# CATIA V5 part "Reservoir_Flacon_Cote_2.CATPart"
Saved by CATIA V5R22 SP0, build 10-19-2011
Part number: Reservoir_Flacon_Cote
Bounding box of the stored display mesh (mm): x 0 to 5, y -31 to 31, z -150 to 150
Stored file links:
  D:\CAO_PER_MODIF_2025\CAO_PER_pick&place_2024P\Sous_Ensemble_Flacon\Reservoir_Flacon\Reservoir_Flacon_Cote_2.CATPart
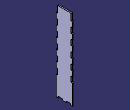
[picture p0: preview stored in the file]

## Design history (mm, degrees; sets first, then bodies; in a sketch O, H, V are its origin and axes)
Body1 (main body)
  Sketch1 on yz-plane, origin (0, 0, 0), H (0, 1, 0), V (0, 0, 1)
    line L1 (-31, 150) -> (31, 150)
    line L2 (31, 150) -> (31, -150)
    line L3 (31, -150) -> (-31, -150)
    line L4 (-31, -150) -> (-31, 150)
    length L4 = 300
    length L1 = 62
    horizontal: L1 H, L3 H
    vertical: L2 V, L4 V
    symmetry: L4 L2 V, L3 L1 H
  Pad1: profile Sketch1, direction (1, 0, 0), length 5
  Sketch2 on end face of Pad1, origin (5, 0, 0), H (0, 1, 0), V (0, 0, 1)
    point P1 (-31, 150)
    line L1 (-31, 150) -> (-26, 150)
    line L2 (-26, 150) -> (-26, 125)
    line L3 (-26, 125) -> (-31, 125)
    line L4 (-31, 125) -> (-31, 150)
    point P2 (-26, 150)
    point P3 (-26, 125)
    point P4 (-31, 125)
    reference projected point E1 (-31, 150) from vertex [face of Pad1 from Sketch1.L1 | end face of Pad1 | face of Pad1 from Sketch1.L4]
    point P5 (31, 150)
    point P6 (26, 150)
    point P7 (26, 125)
    point P8 (31, 125)
    line L5 (31, 150) -> (26, 150)
    line L6 (26, 150) -> (26, 125)
    line L7 (26, 125) -> (31, 125)
    line L8 (31, 125) -> (31, 150)
    length L4 = 25
    length L1 = 5
    horizontal: L1 H, L3 H
    vertical: L2 V, L4 V
    coincidence: P1 E1
    symmetry: P1 P5 V, P2 P6 V, P3 P7 V, P4 P8 V, L1 L5 V, L2 L6 V, L3 L7 V, L4 L8 V
  Pocket1: profile Sketch2, direction (-1, 0, 0), through (limit type 6)
  Sketch3 on end face of Pad1, origin (5, 0, 0), H (0, 1, 0), V (0, 0, 1)
    point P1 (-31, 105)
    line L1 (-31, 105) -> (-26, 105)
    line L2 (-26, 105) -> (-26, 85)
    line L3 (-26, 85) -> (-31, 85)
    line L4 (-31, 85) -> (-31, 105)
    point P2 (-26, 105)
    point P3 (-26, 85)
    point P4 (-31, 85)
    reference projected line E1 (-31, 150) -> (-31, -150) from edge [face of Pad1 from Sketch1.L4 | end face of Pad1]
    reference projected line E2 (-31, 125) -> (-26, 125) from edge [end face of Pad1 | face of Pocket1 from Sketch2.L3]
    point P5 (31, 105)
    point P6 (26, 105)
    point P7 (26, 85)
    point P8 (31, 85)
    line L5 (31, 105) -> (26, 105)
    line L6 (26, 105) -> (26, 85)
    line L7 (26, 85) -> (31, 85)
    line L8 (31, 85) -> (31, 105)
    distance L1 E2 = 20
    length L4 = 20
    length L1 = 5
    horizontal: L1 H, L3 H
    vertical: L2 V, L4 V
    coincidence: L4 E1
    symmetry: P1 P5 V, P2 P6 V, P3 P7 V, P4 P8 V, L1 L5 V, L2 L6 V, L3 L7 V, L4 L8 V
  Pocket2: profile Sketch3, direction (-1, 0, 0), through (limit type 6)
  RectPattern1: of Pocket2, direction 1 instances 5, spacing 40, along edge [face of Pad1 from Sketch1.L4 | end face of Pad1]
  Sketch4 on end face of Pad1, origin (5, 0, 0), H (0, 1, 0), V (0, 0, 1)
    point P1 (-8, -150)
    line L1 (-8, -150) -> (-23, -150)
    line L2 (-23, -150) -> (-23, -145)
    line L3 (-23, -145) -> (-8, -145)
    line L4 (-8, -145) -> (-8, -150)
    point P2 (-23, -150)
    point P3 (-23, -145)
    point P4 (-8, -145)
    reference projected line E1 (-31, -150) -> (31, -150) from edge [face of Pad1 from Sketch1.L3 | end face of Pad1]
    reference projected line E2 (-31, 150) -> (-31, -150) from edge [face of Pad1 from Sketch1.L4 | end face of Pad1]
    point P5 (8, -150)
    point P6 (23, -150)
    point P7 (23, -145)
    point P8 (8, -145)
    line L5 (8, -150) -> (23, -150)
    line L6 (23, -150) -> (23, -145)
    line L7 (23, -145) -> (8, -145)
    line L8 (8, -145) -> (8, -150)
    length L3 = 15
    length L2 = 5
    distance L2 E2 = 8
    horizontal: L1 H, L3 H
    vertical: L2 V, L4 V
    coincidence: L1 E1
    symmetry: P1 P5 V, P2 P6 V, P3 P7 V, P4 P8 V, L1 L5 V, L2 L6 V, L3 L7 V, L4 L8 V
  Pocket3: profile Sketch4, direction (-1, 0, 0), through (limit type 3)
